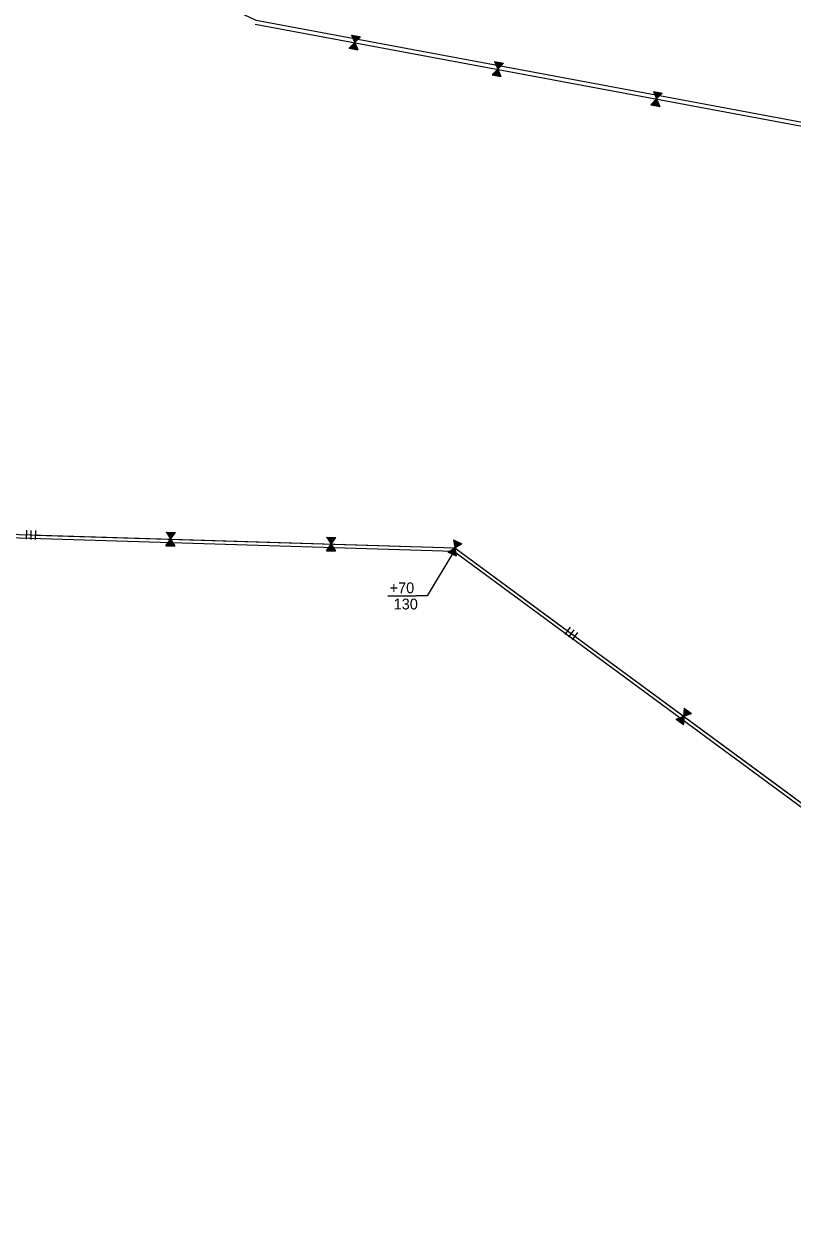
# Model space of a CAD drawing. Extents: x 979729 to 993523, y 1834148 to 1845433.
# Drawn here: x 982362 to 982788, y 1837610 to 1838276 of the extents above; entities that cross this region are included whole.
import ezdxf

# ---------------------------------------------------------------- set-up
doc = ezdxf.new("R2010")
doc.units = 0
for name, color, linetype in [('42', 7, 'Continuous'), ('51', 7, 'Continuous'), ('R_Draft', 7, 'Continuous')]:
    doc.layers.add(name, color=color, linetype=linetype)

msp = doc.modelspace()

# ---------------------------------------------------------------- linework, layer by layer
at = {"layer": '42'}
for p, q in [((982490.19, 1838275.5), (982851.26, 1838208.07)), ((982542.27, 1838262.02), (982545.41, 1838265.24)), ((982543.64, 1838269.39), (982545.41, 1838265.24)), ((982543.69, 1838269.33), (982543.73, 1838269.37)), ((982543.81, 1838269.09), (982544.03, 1838269.32)), ((982543.9, 1838268.83), (982544.33, 1838269.26)), ((982544.02, 1838268.59), (982544.62, 1838269.21)), ((982544.11, 1838268.33), (982544.92, 1838269.15)), ((982544.21, 1838268.07), (982545.21, 1838269.1)), ((982544.33, 1838267.83), (982545.51, 1838269.04)), ((982544.49, 1838267.64), (982545.69, 1838268.87)), ((982544.56, 1838267.35), (982546.1, 1838268.93)), ((982544.68, 1838267.12), (982546.39, 1838268.88)), ((982544.75, 1838266.84), (982546.69, 1838268.82)), ((982544.8, 1838264.56), (982546.2, 1838261.28)), ((982544.89, 1838266.62), (982546.98, 1838268.77)), ((982544.97, 1838266.34), (982547.28, 1838268.71)), ((982544.98, 1838264.77), (982546.49, 1838261.23)), ((982545.09, 1838266.1), (982547.57, 1838268.66)), ((982545.18, 1838265.84), (982547.87, 1838268.6)), ((982545.19, 1838264.92), (982546.79, 1838261.17)), ((982545.32, 1838265.63), (982548.16, 1838268.55)), ((982545.36, 1838265.16), (982547.08, 1838261.12)), ((982545.39, 1838265.34), (982548.46, 1838268.49)), ((982545.41, 1838265.24), (982548.56, 1838268.47)), ((982545.41, 1838265.24), (982547.18, 1838261.1)), ((982542.33, 1838262.06), (982542.36, 1838262)), ((982542.53, 1838262.24), (982542.65, 1838261.94)), ((982542.71, 1838262.45), (982542.95, 1838261.89)), ((982542.91, 1838262.62), (982543.24, 1838261.83)), ((982543.09, 1838262.84), (982543.54, 1838261.78)), ((982543.27, 1838263.05), (982543.84, 1838261.72)), ((982543.47, 1838263.22), (982544.13, 1838261.67)), ((982543.69, 1838263.34), (982544.36, 1838261.77)), ((982543.86, 1838263.58), (982544.72, 1838261.56)), ((982544.05, 1838263.76), (982545.02, 1838261.5)), ((982544.22, 1838264), (982545.31, 1838261.45)), ((982544.43, 1838264.15), (982545.61, 1838261.39)), ((982544.6, 1838264.39), (982545.9, 1838261.34)), ((982622.89, 1838254.66), (982624.65, 1838250.51)), ((982622.93, 1838254.59), (982622.98, 1838254.64)), ((982623.05, 1838254.36), (982623.27, 1838254.59)), ((982623.14, 1838254.1), (982623.57, 1838254.53)), ((982623.27, 1838253.86), (982623.86, 1838254.48)), ((982623.36, 1838253.6), (982624.16, 1838254.42)), ((982623.45, 1838253.34), (982624.45, 1838254.37)), ((982623.57, 1838253.1), (982624.75, 1838254.31)), ((982623.74, 1838252.91), (982624.93, 1838254.14)), ((982623.8, 1838252.62), (982625.34, 1838254.2)), ((982623.92, 1838252.39), (982625.64, 1838254.14)), ((982624, 1838252.11), (982625.93, 1838254.09)), ((982624.14, 1838251.89), (982626.23, 1838254.03)), ((982624.21, 1838251.61), (982626.52, 1838253.98)), ((982624.33, 1838251.37), (982626.82, 1838253.92)), ((982624.42, 1838251.11), (982627.11, 1838253.87)), ((982624.56, 1838250.89), (982627.41, 1838253.81)), ((982624.63, 1838250.61), (982627.7, 1838253.76)), ((982624.65, 1838250.51), (982627.8, 1838253.74)), ((982621.51, 1838247.29), (982624.65, 1838250.51)), ((982621.57, 1838247.33), (982621.6, 1838247.27)), ((982621.77, 1838247.5), (982621.9, 1838247.21)), ((982621.95, 1838247.72), (982622.19, 1838247.16)), ((982622.15, 1838247.89), (982622.49, 1838247.1)), ((982622.33, 1838248.1), (982622.78, 1838247.05)), ((982622.51, 1838248.31), (982623.08, 1838246.99)), ((982622.71, 1838248.49), (982623.37, 1838246.94)), ((982622.93, 1838248.61), (982623.6, 1838247.04)), ((982623.1, 1838248.85), (982623.96, 1838246.83)), ((982623.3, 1838249.03), (982624.26, 1838246.77)), ((982623.47, 1838249.27), (982624.55, 1838246.72)), ((982623.67, 1838249.42), (982624.85, 1838246.66)), ((982623.84, 1838249.65), (982625.14, 1838246.61)), ((982624.04, 1838249.83), (982625.44, 1838246.55)), ((982624.22, 1838250.04), (982625.73, 1838246.5)), ((982624.43, 1838250.19), (982626.03, 1838246.44)), ((982624.6, 1838250.43), (982626.33, 1838246.39)), ((982624.65, 1838250.51), (982626.42, 1838246.37)), ((982710.9, 1838238.1), (982712.67, 1838233.96)), ((982710.95, 1838238.04), (982710.99, 1838238.08)), ((982711.07, 1838237.8), (982711.29, 1838238.03)), ((982711.16, 1838237.54), (982711.59, 1838237.97)), ((982711.28, 1838237.3), (982711.88, 1838237.92)), ((982711.37, 1838237.04), (982712.18, 1838237.86)), ((982709.53, 1838230.73), (982712.67, 1838233.96)), ((982710.17, 1838231.33), (982710.5, 1838230.55)), ((982710.35, 1838231.55), (982710.8, 1838230.49)), ((982710.53, 1838231.76), (982711.09, 1838230.43)), ((982710.73, 1838231.93), (982711.39, 1838230.38)), ((982710.95, 1838232.05), (982711.62, 1838230.48)), ((982711.12, 1838232.3), (982711.98, 1838230.27)), ((982711.31, 1838232.47), (982712.28, 1838230.21)), ((982711.47, 1838236.78), (982712.47, 1838237.81)), ((982711.48, 1838232.71), (982712.57, 1838230.16)), ((982711.59, 1838236.54), (982712.77, 1838237.75)), ((982711.69, 1838232.86), (982712.87, 1838230.1)), ((982711.75, 1838236.35), (982712.95, 1838237.58)), ((982711.82, 1838236.06), (982713.36, 1838237.64)), ((982711.86, 1838233.1), (982713.16, 1838230.05)), ((982711.94, 1838235.83), (982713.65, 1838237.59)), ((982712.01, 1838235.55), (982713.95, 1838237.53)), ((982712.06, 1838233.27), (982713.46, 1838229.99)), ((982712.15, 1838235.33), (982714.24, 1838237.48)), ((982712.23, 1838235.05), (982714.54, 1838237.42)), ((982712.24, 1838233.48), (982713.75, 1838229.94)), ((982712.35, 1838234.82), (982714.83, 1838237.37)), ((982712.44, 1838234.55), (982715.13, 1838237.31)), ((982712.45, 1838233.63), (982714.05, 1838229.88)), ((982712.58, 1838234.34), (982715.42, 1838237.26)), ((982712.62, 1838233.87), (982714.34, 1838229.83)), ((982712.65, 1838234.05), (982715.72, 1838237.2)), ((982712.67, 1838233.96), (982715.82, 1838237.18)), ((982712.67, 1838233.96), (982714.44, 1838229.81)), ((982709.59, 1838230.77), (982709.62, 1838230.71)), ((982709.79, 1838230.95), (982709.91, 1838230.66)), ((982709.97, 1838231.16), (982710.21, 1838230.6)), ((982197.75, 1837997.51), (982600.97, 1837985.09)), ((982363.55, 1837994.9), (982363.4, 1837989.91)), ((982366.05, 1837994.83), (982365.89, 1837989.83)), ((982368.55, 1837994.75), (982368.39, 1837989.75)), ((982441.05, 1837993.77), (982443.43, 1837989.94)), ((982441.11, 1837993.71), (982441.14, 1837993.77)), ((982441.26, 1837993.5), (982441.44, 1837993.76)), ((982441.39, 1837993.25), (982441.74, 1837993.75)), ((982441.55, 1837993.04), (982442.05, 1837993.74)), ((982441.68, 1837992.79), (982442.35, 1837993.73)), ((982441.81, 1837992.55), (982442.65, 1837993.72)), ((982441.97, 1837992.34), (982442.95, 1837993.71)), ((982442.16, 1837992.17), (982443.15, 1837993.57)), ((982442.27, 1837991.9), (982443.55, 1837993.69)), ((982442.42, 1837991.68), (982443.85, 1837993.68)), ((982442.54, 1837991.42), (982444.15, 1837993.67)), ((982442.71, 1837991.23), (982444.45, 1837993.66)), ((982442.83, 1837990.96), (982444.75, 1837993.66)), ((982442.98, 1837990.74), (982445.05, 1837993.65)), ((982443.11, 1837990.5), (982445.35, 1837993.64)), ((982443.28, 1837990.31), (982445.65, 1837993.63)), ((982443.4, 1837990.04), (982445.95, 1837993.62)), ((982443.43, 1837989.94), (982446.05, 1837993.62)), ((982440.82, 1837986.27), (982443.43, 1837989.94)), ((982440.88, 1837986.33), (982440.91, 1837986.27)), ((982441.05, 1837986.53), (982441.21, 1837986.26)), ((982441.19, 1837986.77), (982441.51, 1837986.25)), ((982441.36, 1837986.97), (982441.81, 1837986.24)), ((982441.51, 1837987.21), (982442.11, 1837986.23)), ((982441.65, 1837987.44), (982442.42, 1837986.22)), ((982441.82, 1837987.65), (982442.71, 1837986.21)), ((982442.02, 1837987.8), (982442.93, 1837986.35)), ((982442.15, 1837988.07), (982443.32, 1837986.2)), ((982442.32, 1837988.27), (982443.62, 1837986.19)), ((982442.45, 1837988.53), (982443.92, 1837986.18)), ((982442.63, 1837988.71), (982444.22, 1837986.17)), ((982442.76, 1837988.97), (982444.52, 1837986.16)), ((982442.93, 1837989.17), (982444.82, 1837986.15)), ((982443.08, 1837989.41), (982445.12, 1837986.14)), ((982443.26, 1837989.59), (982445.42, 1837986.13)), ((982443.39, 1837989.85), (982445.72, 1837986.12)), ((982443.43, 1837989.94), (982445.82, 1837986.12)), ((982529.73, 1837983.49), (982532.34, 1837987.16)), ((982529.96, 1837990.98), (982532.34, 1837987.16)), ((982530.01, 1837990.93), (982530.05, 1837990.98)), ((982530.17, 1837990.71), (982530.35, 1837990.97)), ((982530.3, 1837990.47), (982530.65, 1837990.96)), ((982530.46, 1837990.25), (982530.95, 1837990.95)), ((982530.59, 1837990.01), (982531.25, 1837990.94)), ((982530.72, 1837989.76), (982531.55, 1837990.93)), ((982530.87, 1837989.55), (982531.85, 1837990.92)), ((982531.06, 1837985.28), (982532.22, 1837983.41)), ((982531.07, 1837989.39), (982532.06, 1837990.78)), ((982531.18, 1837989.11), (982532.45, 1837990.9)), ((982531.23, 1837985.48), (982532.52, 1837983.4)), ((982531.33, 1837988.9), (982532.75, 1837990.9)), ((982531.36, 1837985.74), (982532.82, 1837983.39)), ((982531.45, 1837988.63), (982533.05, 1837990.89)), ((982531.54, 1837985.92), (982533.12, 1837983.38)), ((982531.62, 1837988.44), (982533.36, 1837990.88)), ((982531.67, 1837986.18), (982533.42, 1837983.37)), ((982531.73, 1837988.17), (982533.66, 1837990.87)), ((982531.84, 1837986.39), (982533.72, 1837983.36)), ((982531.89, 1837987.96), (982533.95, 1837990.86)), ((982531.99, 1837986.62), (982534.02, 1837983.35)), ((982532.02, 1837987.71), (982534.25, 1837990.85)), ((982532.17, 1837986.8), (982534.32, 1837983.34)), ((982532.19, 1837987.52), (982534.56, 1837990.84)), ((982532.3, 1837987.07), (982534.62, 1837983.33)), ((982532.31, 1837987.25), (982534.86, 1837990.83)), ((982532.34, 1837987.16), (982534.96, 1837990.83)), ((982532.34, 1837987.16), (982534.72, 1837983.33)), ((982600.19, 1837989.51), (982600.92, 1837985.07)), ((982600.22, 1837989.44), (982600.28, 1837989.48)), ((982600.28, 1837989.18), (982600.55, 1837989.35)), ((982600.31, 1837988.91), (982600.82, 1837989.23)), ((982600.37, 1837988.65), (982601.1, 1837989.1)), ((982600.4, 1837988.37), (982601.37, 1837988.98)), ((982600.43, 1837988.09), (982601.65, 1837988.85)), ((982600.49, 1837987.84), (982601.92, 1837988.73)), ((982600.6, 1837987.62), (982602.05, 1837988.52)), ((982600.6, 1837987.32), (982602.47, 1837988.48)), ((982600.66, 1837987.06), (982602.74, 1837988.36)), ((982600.66, 1837986.77), (982603.01, 1837988.24)), ((982600.75, 1837986.53), (982603.29, 1837988.11)), ((982600.75, 1837986.23), (982603.56, 1837987.99)), ((982600.81, 1837985.98), (982603.83, 1837987.86)), ((982600.84, 1837985.7), (982604.11, 1837987.74)), ((982600.92, 1837985.46), (982604.38, 1837987.62)), ((982600.92, 1837985.07), (982604.75, 1837987.45)), ((982600.93, 1837985.17), (982604.66, 1837987.49)), ((982529.79, 1837983.54), (982529.82, 1837983.48)), ((982529.95, 1837983.74), (982530.12, 1837983.47)), ((982530.1, 1837983.98), (982530.42, 1837983.46)), ((982530.27, 1837984.18), (982530.72, 1837983.45)), ((982530.41, 1837984.42), (982531.02, 1837983.45)), ((982530.56, 1837984.66), (982531.32, 1837983.44)), ((982530.73, 1837984.86), (982531.62, 1837983.43)), ((982530.93, 1837985.01), (982531.83, 1837983.56)), ((982597.1, 1837982.68), (982600.92, 1837985.07)), ((982597.17, 1837982.71), (982597.18, 1837982.64)), ((982597.4, 1837982.83), (982597.46, 1837982.52)), ((982597.63, 1837982.99), (982597.73, 1837982.4)), ((982597.86, 1837983.12), (982598, 1837982.27)), ((982598.09, 1837983.28), (982598.28, 1837982.15)), ((982598.32, 1837983.44), (982598.55, 1837982.02)), ((982598.55, 1837983.57), (982598.82, 1837981.9)), ((982598.79, 1837983.63), (982599.07, 1837981.94)), ((982599.01, 1837983.83), (982599.37, 1837981.65)), ((982599.25, 1837983.95), (982599.65, 1837981.53)), ((982599.47, 1837984.14), (982599.92, 1837981.4)), ((982599.71, 1837984.23), (982600.19, 1837981.28)), ((982599.93, 1837984.43), (982600.47, 1837981.16)), ((982600.16, 1837984.55), (982600.74, 1837981.03)), ((982600.39, 1837984.71), (982601.01, 1837980.91)), ((982600.63, 1837984.81), (982601.29, 1837980.78)), ((982600.85, 1837985), (982601.56, 1837980.66)), ((982600.92, 1837985.07), (982601.65, 1837980.62)), ((982600.97, 1837985.09), (982865.65, 1837790.18)), ((982664.77, 1837941.21), (982661.8, 1837937.19)), ((982666.78, 1837939.73), (982663.82, 1837935.71)), ((982668.79, 1837938.25), (982665.83, 1837934.22)), ((982727.91, 1837896.27), (982727.7, 1837891.76)), ((982727.7, 1837891.76), (982731.94, 1837893.3)), ((982727.73, 1837891.86), (982731.86, 1837893.36)), ((982727.75, 1837892.4), (982731.37, 1837893.72)), ((982727.78, 1837892.94), (982730.89, 1837894.07)), ((982727.78, 1837892.68), (982731.13, 1837893.89)), ((982727.78, 1837892.15), (982731.62, 1837893.54)), ((982727.8, 1837893.48), (982730.41, 1837894.43)), ((982727.84, 1837893.23), (982730.65, 1837894.25)), ((982727.85, 1837894.83), (982729.2, 1837895.32)), ((982727.85, 1837894.57), (982729.44, 1837895.14)), ((982727.85, 1837894.03), (982729.92, 1837894.78)), ((982727.86, 1837893.77), (982730.17, 1837894.61)), ((982727.88, 1837895.11), (982728.96, 1837895.5)), ((982727.9, 1837895.65), (982728.47, 1837895.85)), ((982727.91, 1837895.38), (982728.71, 1837895.68)), ((982727.92, 1837894.32), (982729.53, 1837894.91)), ((982727.93, 1837896.19), (982727.99, 1837896.21)), ((982727.93, 1837895.92), (982728.23, 1837896.03)), ((982723.47, 1837890.23), (982727.7, 1837891.76)), ((982723.54, 1837890.24), (982723.54, 1837890.17)), ((982723.8, 1837890.31), (982723.78, 1837889.99)), ((982724.05, 1837890.42), (982724.02, 1837889.81)), ((982724.31, 1837890.49), (982724.27, 1837889.64)), ((982724.56, 1837890.61), (982724.51, 1837889.46)), ((982724.82, 1837890.72), (982724.75, 1837889.28)), ((982725.07, 1837890.79), (982724.99, 1837889.1)), ((982725.32, 1837890.8), (982725.24, 1837889.09)), ((982725.58, 1837890.95), (982725.48, 1837888.75)), ((982725.83, 1837891.02), (982725.72, 1837888.57)), ((982726.09, 1837891.16), (982725.96, 1837888.39)), ((982726.34, 1837891.2), (982726.2, 1837888.21)), ((982726.6, 1837891.34), (982726.44, 1837888.03)), ((982726.85, 1837891.41), (982726.69, 1837887.86)), ((982727.11, 1837891.53), (982726.93, 1837887.68)), ((982727.36, 1837891.57), (982727.17, 1837887.5)), ((982727.62, 1837891.71), (982727.41, 1837887.32)), ((982727.7, 1837891.76), (982727.49, 1837887.26))]:
    msp.add_line(p, q, dxfattribs=at)
for points in [[(982490.19, 1838275.5), (982786.4, 1838220.19)], [(982543.64, 1838269.39), (982548.56, 1838268.47)], [(982542.27, 1838262.02), (982547.18, 1838261.1)], [(982622.89, 1838254.66), (982627.8, 1838253.74)], [(982621.51, 1838247.29), (982626.42, 1838246.37)], [(982710.9, 1838238.1), (982715.82, 1838237.18)], [(982709.53, 1838230.73), (982714.44, 1838229.81)], [(982368.47, 1837992.25), (982600.97, 1837985.09)], [(982441.05, 1837993.77), (982446.05, 1837993.62)], [(982440.82, 1837986.27), (982445.82, 1837986.12)], [(982529.96, 1837990.98), (982534.96, 1837990.83)], [(982600.19, 1837989.51), (982604.75, 1837987.45)], [(982529.73, 1837983.49), (982534.72, 1837983.33)], [(982597.1, 1837982.68), (982601.65, 1837980.62)], [(982600.97, 1837985.09), (982661.27, 1837940.68)], [(982667.31, 1837936.24), (982788.09, 1837847.29)], [(982727.91, 1837896.27), (982731.94, 1837893.3)], [(982723.47, 1837890.23), (982727.49, 1837887.26)]]:
    msp.add_lwpolyline(points, dxfattribs=at)
at = {"layer": '51'}
for points in [[(983839.63, 1837883.59), (982851.76, 1838210.02), (982490.82, 1838277.42), (982183.3, 1838422.69)], [(983832.14, 1837610.35), (983652.57, 1837707.14), (983510.47, 1837676.41), (983408.2, 1837770.04), (983207.39, 1837710.64), (983118.6, 1837831.53), (982865.15, 1837788.06), (982600.28, 1837983.11), (982196.59, 1837995.54), (982113.58, 1838135.58), (981690.98, 1838258.2), (981584.78, 1838227.65)]]:
    msp.add_lwpolyline(points, dxfattribs=at)
at = {"layer": 'R_Draft'}
msp.add_line((982563.69, 1837958.48), (982579.49, 1837958.48), dxfattribs=at)
msp.add_lwpolyline([(982600.28, 1837983.11), (982585.49, 1837958.48), (982579.49, 1837958.48)], dxfattribs=at)

# ---------------------------------------------------------------- texts
for s, p in [('+70', (982564.77, 1837959.98)), (' 130', (982564.77, 1837950.98))]:
    msp.add_text(s, height=6, rotation=360, dxfattribs=at).set_placement(p)

doc.saveas('drawing.dxf')
